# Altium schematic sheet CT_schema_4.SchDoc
size 382 x 218 mm
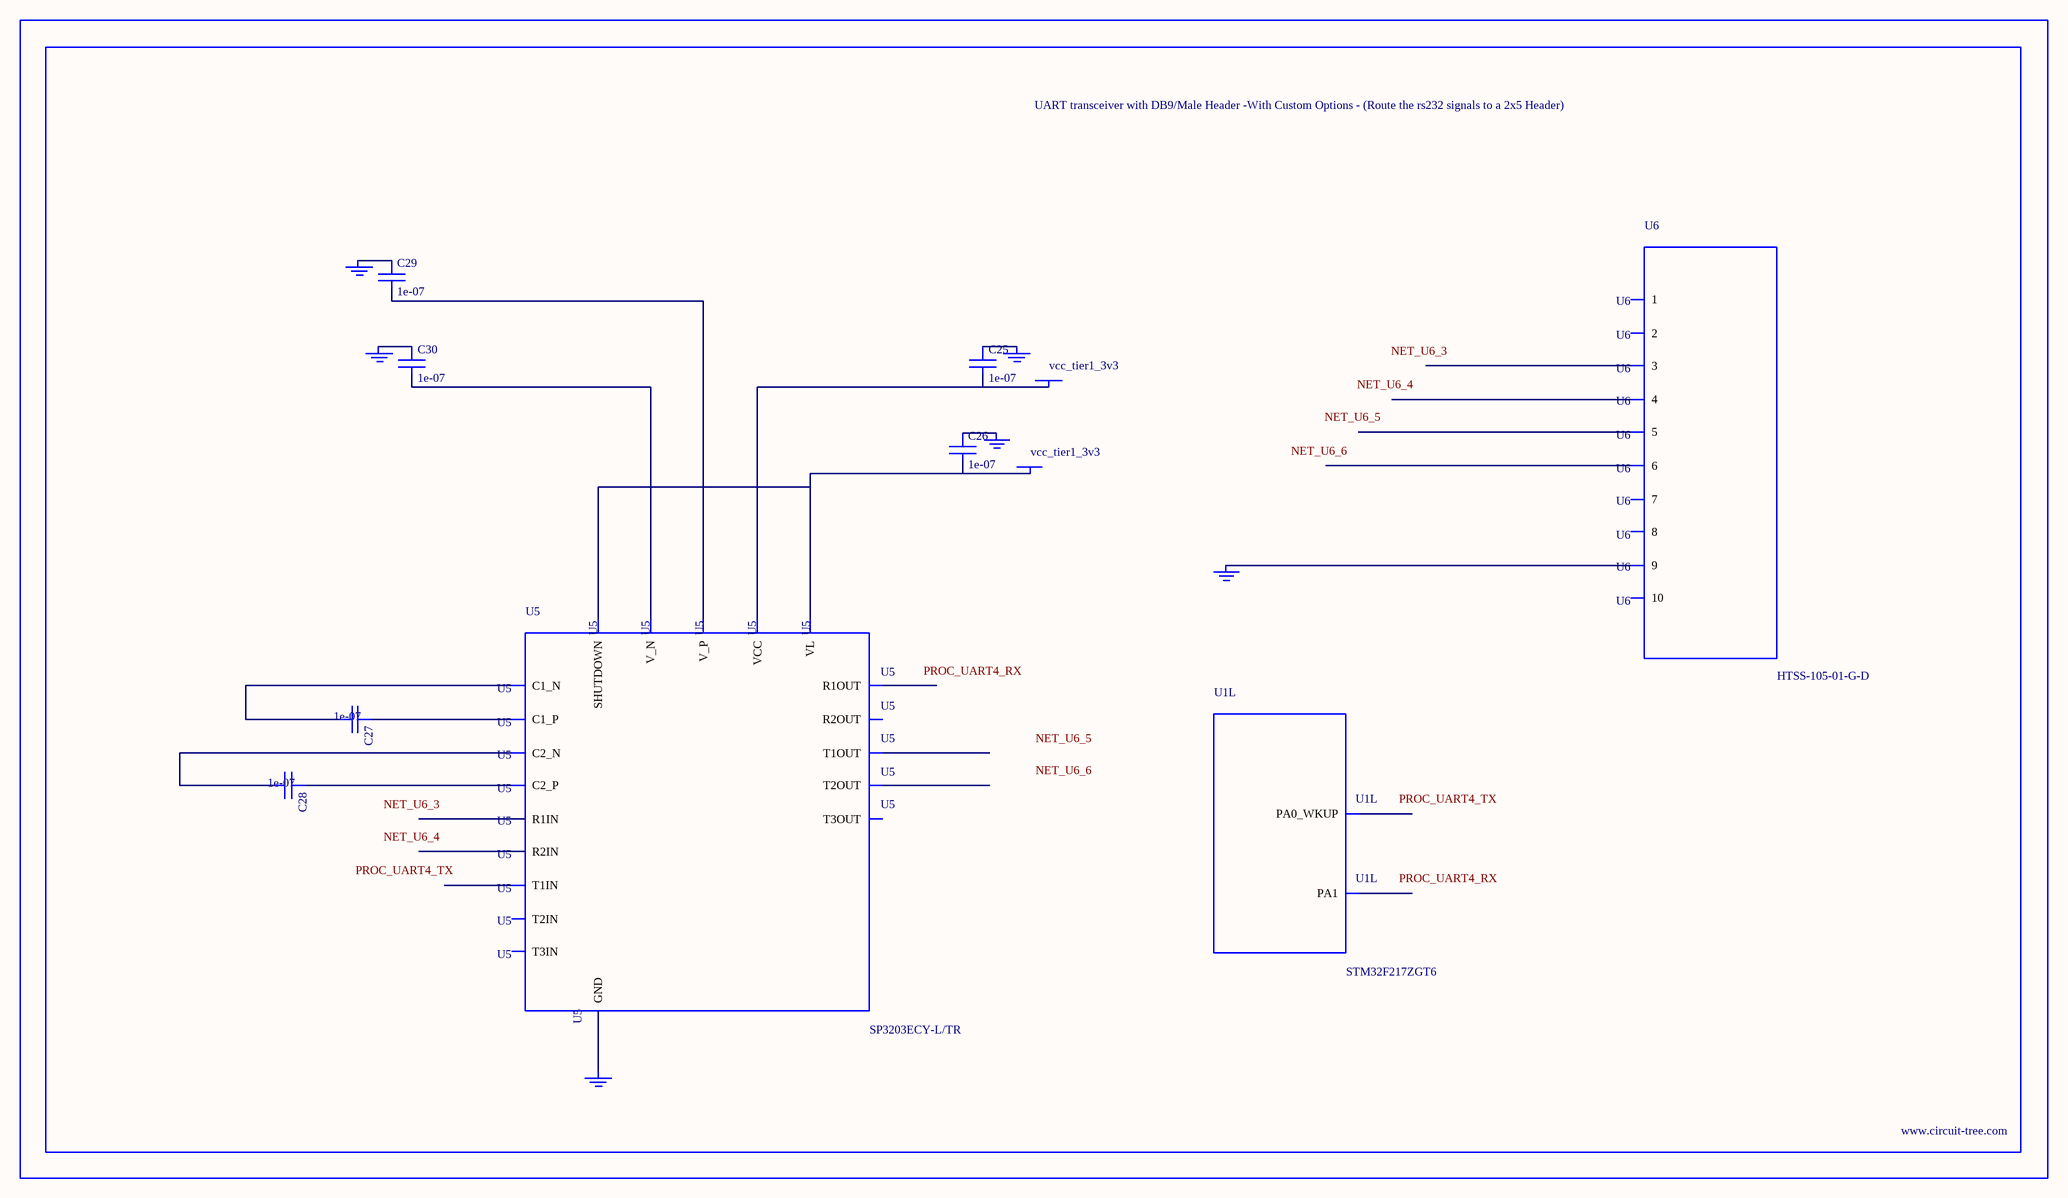
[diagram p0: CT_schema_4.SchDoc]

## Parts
BORDER3  (no value)
C25  1e-07  [C0402]
C26  1e-07  [C0402]
C27  1e-07  [C0402]
C28  1e-07  [C0402]
C29  1e-07  [C0402]
C30  1e-07  [C0402]
GND_INSTANCE_3_0  (no value)
GND_INSTANCE_3_1  (no value)
GND_INSTANCE_3_2  (no value)
GND_INSTANCE_3_3  (no value)
GND_INSTANCE_3_4  (no value)
GND_INSTANCE_3_5  (no value)
POWER_INSTANCE_3_0  vcc_tier1_3v3
POWER_INSTANCE_3_1  vcc_tier1_3v3
U1  STM32F217ZGT6  [LQFP144]  (part L of 13)
U5  SP3203ECY-L/TR  [TSSOP20-I]
U6  HTSS-105-01-G-D  [HTSS-105-01-G-D]

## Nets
NetC25_1: C25.1 GND_INSTANCE_3_3.0(GND)
NetC25_2: C25.2 POWER_INSTANCE_3_1.0(PWR) U5.19(VCC)
NetC26_1: C26.1 GND_INSTANCE_3_2.0(GND)
NetC26_2: C26.2 POWER_INSTANCE_3_0.0(PWR) U5.12(VL) U5.20(SHUTDOWN)
NetC27_1: C27.1 U5.1(C1_P)
NetC27_2: C27.2 U5.3(C1_N)
NetC28_1: C28.1 U5.4(C2_P)
NetC28_2: C28.2 U5.5(C2_N)
NetC29_1: C29.1 GND_INSTANCE_3_0.0(GND)
NetC29_2: C29.2 U5.2(V_P)
NetC30_1: C30.1 GND_INSTANCE_3_1.0(GND)
NetC30_2: C30.2 U5.6(V_N)
NetGND_INSTANCE_3_4_0: GND_INSTANCE_3_4.0(GND) U5.18(GND)
NetGND_INSTANCE_3_5_0: GND_INSTANCE_3_5.0(GND) U6.9

Not connected (* = marked no-connect by the designer): U1 34(PA0_WKUP) 35(PA1); U5 7(T1IN) 8(T2IN) 9(T3IN) 10(R2OUT) 11(R1OUT) 13(R2IN) 14(R1IN) 15(T3OUT) 16(T2OUT) 17(T1OUT); U6 1 2 3 4 5 6 7 8 10

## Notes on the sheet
- Labels drawn without touching a wire or pin: NET_U6_3, NET_U6_4, NET_U6_5, NET_U6_6, PROC_UART4_RX, PROC_UART4_TX

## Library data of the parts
BORDER3 = BORDER_PAGE3
C25-C30 = C0402C104K3RACTU
GND_INSTANCE_3_0-GND_INSTANCE_3_5 = GND
POWER_INSTANCE_3_0 POWER_INSTANCE_3_1 = PWR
